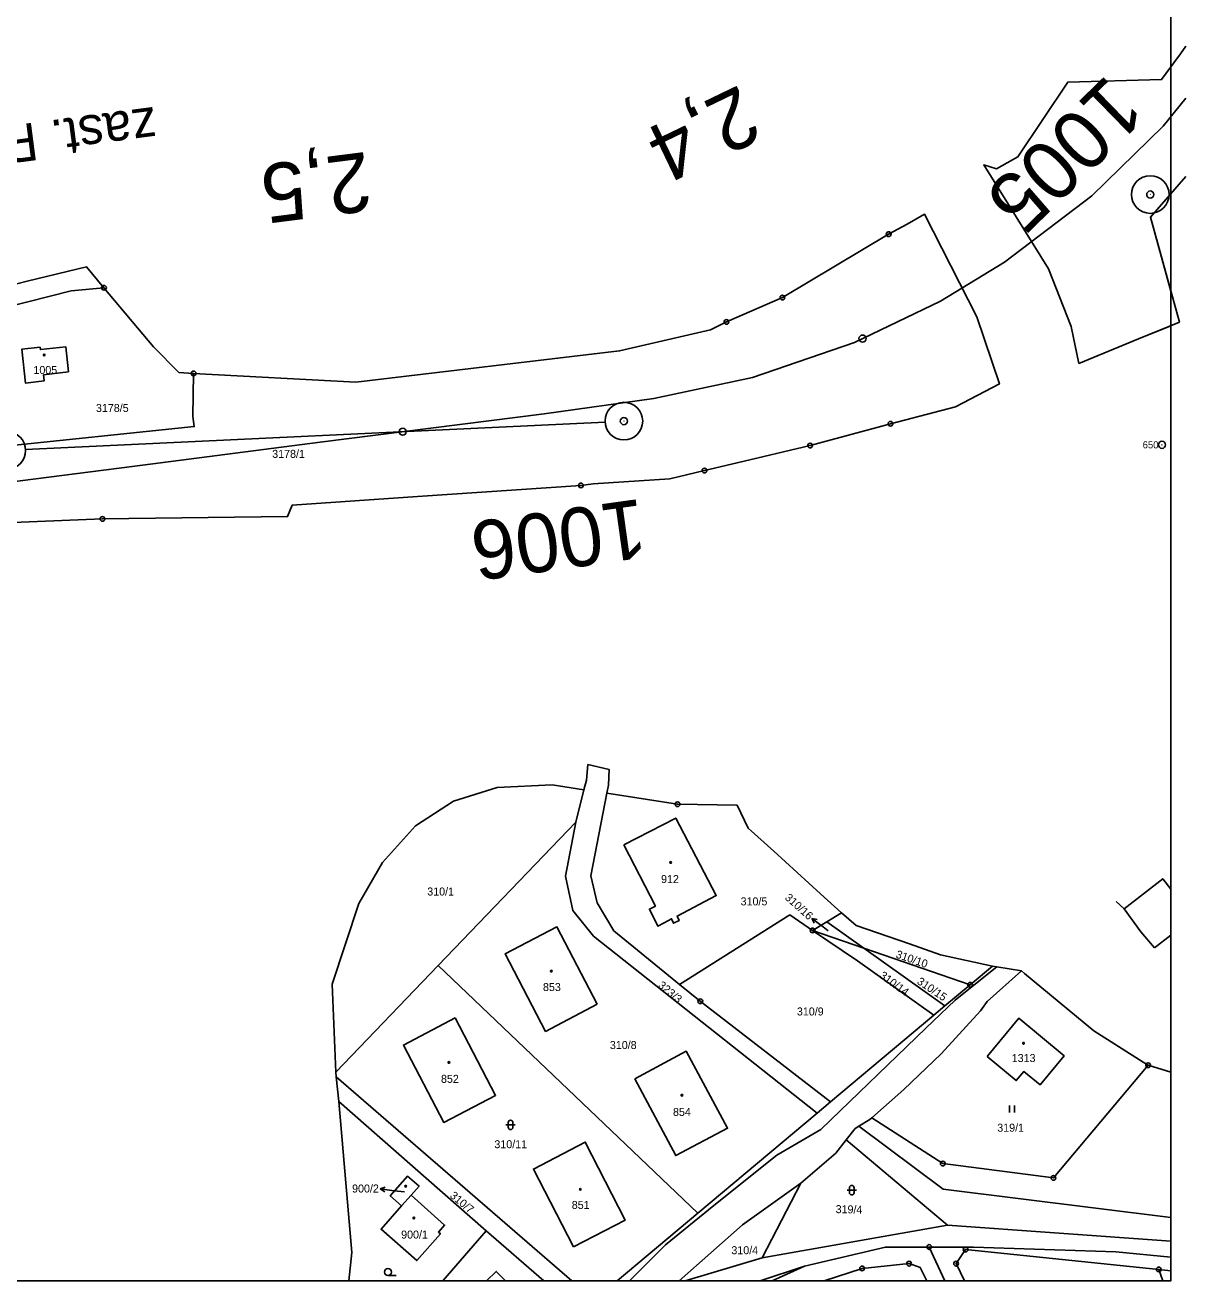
# Model space of a CAD drawing. Extents: x -728802 to -728097, y -1073200 to -1072700.
# Drawn here: x -728343.6 to -728096.8, y -1073200 to -1072933.2 of the extents above; entities that cross this region are included whole.
import ezdxf

# ---------------------------------------------------------------- set-up
doc = ezdxf.new("R2010")
doc.units = 0
for name, color, linetype in [('A5_JŽM', 7, 'Continuous'), ('body_ZBP', 7, 'Continuous'), ('Hranice parcel', 7, 'Continuous'), ('K_31_listy_JŽM', 7, 'Continuous'), ('Pop  PČ popisy', 7, 'Continuous')]:
    doc.layers.add(name, color=color, linetype=linetype)

msp = doc.modelspace()

# ---------------------------------------------------------------- linework, layer by layer
at = {"layer": 'A5_JŽM'}
msp.add_line((-728160.01, -1072977.57), (-728159.91, -1072977.57), dxfattribs=at)
for points in [[(-728096.8, -1072965.33), (-728104.34, -1072973.98), (-728098.16, -1072996.31), (-728106.84, -1072999.82), (-728119.54, -1073005.05), (-728121.2, -1072997.23), (-728125.99, -1072984.92), (-728139.74, -1072962.82), (-728137.07, -1072963.68), (-728132.51, -1072961.17), (-728121.91, -1072945.25), (-728101.97, -1072944.72), (-728097.95, -1072939.25), (-728096.8, -1072937.65)], [(-728096.8, -1072948.67), (-728101.61, -1072954.64), (-728116.81, -1072969.46), (-728135.35, -1072983.51), (-728148.98, -1072991.79), (-728167.22, -1073000.57), (-728188.91, -1073008), (-728209.93, -1073012.47), (-728233.25, -1073015.72), (-728280.82, -1073021.79), (-728320.8, -1073026.91), (-728374.01, -1073033.72)], [(-728326.79, -1072988.95), (-728316.3, -1073001.5), (-728310.91, -1073006.97), (-728307.76, -1073007.16), (-728273.27, -1073008.99), (-728217.2, -1073002.39), (-728197.86, -1072997.89), (-728194.47, -1072996.23), (-728182.58, -1072991.05), (-728160.01, -1072977.6), (-728156.05, -1072975.45), (-728152.39, -1072973.29), (-728141.21, -1072995.16), (-728136.45, -1073009.39), (-728145.77, -1073014.29), (-728159.61, -1073017.87), (-728176.68, -1073022.51), (-728192.2, -1073026.16), (-728199.14, -1073027.8), (-728206.51, -1073029.56), (-728222.82, -1073030.66), (-728225.41, -1073030.96), (-728260.11, -1073033.32), (-728286.78, -1073035.13), (-728287.77, -1073037.59), (-728327.13, -1073038.08), (-728361.73, -1073039.5)], [(-728498.81, -1073037.92), (-728499.78, -1073032.61), (-728497.54, -1073030.15), (-728493.68, -1073027.94), (-728443.97, -1073014.59), (-728443.68, -1073014.51), (-728441.09, -1073023.23), (-728428.92, -1073019.94), (-728429.82, -1073016.43), (-728427.49, -1073015.84), (-728421.24, -1073014.23), (-728422.34, -1073010.27), (-728422.77, -1073008.34), (-728418.21, -1073007), (-728380.57, -1072997.2), (-728343.1, -1072987.57), (-728330.49, -1072984.52), (-728326.79, -1072988.95)]]:
    msp.add_lwpolyline(points, dxfattribs=at)
for centre, radius in [((-728159.96, -1072977.57), 0.499), ((-728165.54, -1072999.76), 0.75), ((-728263.28, -1073019.55), 0.75)]:
    msp.add_circle(centre, radius, dxfattribs=at)
at = {"layer": 'body_ZBP'}
for p, q in [((-728104.34, -1072969.11), (-728104.41, -1072969.18)), ((-728343.46, -1073023.35), (-728220.26, -1073017.49)), ((-728216.22, -1073017.29), (-728216.31, -1073017.3))]:
    msp.add_line(p, q, dxfattribs=at)
for centre, radius in [((-728104.37, -1072969.15), 4), ((-728104.37, -1072969.15), 0.756), ((-728216.27, -1073017.3), 4), ((-728216.27, -1073017.3), 0.756), ((-728347.46, -1073023.54), 4)]:
    msp.add_circle(centre, radius, dxfattribs=at)
at = {"layer": 'Hranice parcel'}
for p, q in [((-728176.68, -1073022.51), (-728192.19, -1073026.18)), ((-728192.19, -1073026.18), (-728199.14, -1073027.8)), ((-728226.46, -1073102.53), (-728224.75, -1073095.65)), ((-728255.72, -1073132.95), (-728226.46, -1073102.53)), ((-728109.91, -1073120.91), (-728101.72, -1073114.55)), ((-728101.72, -1073114.55), (-728100, -1073116.76)), ((-728109.91, -1073120.91), (-728111.61, -1073119.36)), ((-728204.42, -1073137), (-728180.96, -1073122.24)), ((-728180.96, -1073122.24), (-728176.14, -1073125.53)), ((-728173.13, -1073123.69), (-728169.99, -1073121.77)), ((-728166.88, -1073124.49), (-728169.99, -1073121.77)), ((-728176.14, -1073125.53), (-728173.13, -1073123.69)), ((-728173.13, -1073123.69), (-728165.28, -1073129.28)), ((-728165.28, -1073129.28), (-728176.14, -1073125.53)), ((-728166.58, -1073132), (-728176.14, -1073125.53)), ((-728103.47, -1073129.22), (-728106.4, -1073125.8)), ((-728100, -1073126.52), (-728103.47, -1073129.22)), ((-728103.47, -1073129.22), (-728100, -1073126.52)), ((-728148.01, -1073141.57), (-728165.28, -1073129.28)), ((-728165.28, -1073129.28), (-728142.67, -1073137.09)), ((-728277.54, -1073155.64), (-728255.72, -1073132.95)), ((-728255.72, -1073132.95), (-728200.53, -1073185.62)), ((-728150.39, -1073143.57), (-728166.58, -1073132)), ((-728137.92, -1073133.11), (-728148.93, -1073130.68)), ((-728142.67, -1073137.09), (-728137.92, -1073133.11)), ((-728136.99, -1073133.27), (-728137.92, -1073133.11)), ((-728136.99, -1073133.27), (-728137.64, -1073133.79)), ((-728131.74, -1073134.15), (-728136.99, -1073133.27)), ((-728131.09, -1073134.68), (-728131.74, -1073134.15)), ((-728142.67, -1073137.09), (-728148.01, -1073141.57)), ((-728172.33, -1073161.97), (-728150.39, -1073143.57)), ((-728148.01, -1073141.57), (-728150.39, -1073143.57)), ((-728124.97, -1073178.11), (-728104.83, -1073154.17)), ((-728277.54, -1073155.64), (-728277.43, -1073156.67)), ((-728227.3, -1073200), (-728277.43, -1073156.67)), ((-728277.43, -1073156.67), (-728276.88, -1073161.86)), ((-728245.52, -1073189.36), (-728276.88, -1073161.86)), ((-728175.16, -1073164.35), (-728172.33, -1073161.97)), ((-728200.53, -1073185.62), (-728175.16, -1073164.35)), ((-728164, -1073165.73), (-728163.55, -1073165.34)), ((-728134.26, -1073164.22), (-728134.26, -1073162.72)), ((-728133.26, -1073164.22), (-728133.26, -1073162.72)), ((-728241.37, -1073166.86), (-728239.37, -1073166.86)), ((-728240.87, -1073166.36), (-728240.87, -1073167.36)), ((-728239.87, -1073167.36), (-728239.87, -1073166.36)), ((-728166.31, -1073167.13), (-728164, -1073165.73)), ((-728169.03, -1073170.06), (-728171.2, -1073172.84)), ((-728147.48, -1073188.16), (-728169.03, -1073170.06)), ((-728171.2, -1073172.84), (-728178.64, -1073179.24)), ((-728178.64, -1073179.24), (-728191.04, -1073188.08)), ((-728186.87, -1073195.13), (-728178.64, -1073179.24)), ((-728168.82, -1073180.72), (-728166.82, -1073180.72)), ((-728168.32, -1073180.22), (-728168.32, -1073181.22)), ((-728167.32, -1073181.22), (-728167.32, -1073180.22)), ((-728261.51, -1073181.82), (-728263.51, -1073184.08)), ((-728217.67, -1073200), (-728200.53, -1073185.62)), ((-728245.52, -1073189.36), (-728254.78, -1073200)), ((-728191.04, -1073188.08), (-728204.54, -1073200)), ((-728186.87, -1073195.13), (-728147.48, -1073188.16)), ((-728148.01, -1073200), (-728151.36, -1073192.8)), ((-728203.27, -1073200), (-728186.87, -1073195.13)), ((-728266.43, -1073198.87), (-728264.68, -1073198.87)), ((-728102.56, -1073197.57), (-728101.69, -1073200))]:
    msp.add_line(p, q, dxfattribs=at)
for points in [[(-728100, -1072942.04), (-728101.97, -1072944.72), (-728121.91, -1072945.25), (-728132.51, -1072961.17), (-728137.07, -1072963.68), (-728139.74, -1072962.82), (-728125.99, -1072984.92), (-728121.2, -1072997.23), (-728119.54, -1073005.05), (-728106.84, -1072999.82), (-728100, -1072997.05)], [(-728100, -1072989.66), (-728104.34, -1072973.98), (-728100, -1072969)], [(-728361.73, -1073039.5), (-728327.13, -1073038.08), (-728287.77, -1073037.59), (-728286.78, -1073035.13), (-728260.11, -1073033.32), (-728225.41, -1073030.96), (-728222.82, -1073030.66), (-728206.51, -1073029.56), (-728199.14, -1073027.8), (-728192.2, -1073026.16), (-728176.68, -1073022.51), (-728159.61, -1073017.87), (-728145.77, -1073014.29), (-728136.45, -1073009.39), (-728141.21, -1072995.16), (-728152.39, -1072973.29), (-728156.05, -1072975.45), (-728160.01, -1072977.6), (-728182.58, -1072991.05), (-728194.47, -1072996.23), (-728197.86, -1072997.89), (-728217.2, -1073002.39), (-728273.27, -1073008.99), (-728307.76, -1073007.16)], [(-728326.79, -1072988.95), (-728330.49, -1072984.52), (-728343.1, -1072987.57)], [(-728343.1, -1072987.57), (-728380.57, -1072997.2), (-728418.21, -1073007)], [(-728326.79, -1072988.95), (-728333.76, -1072989.63), (-728347.72, -1072993.16)], [(-728307.76, -1073007.16), (-728310.91, -1073006.97), (-728316.3, -1073001.5), (-728326.79, -1072988.95)], [(-728334.31, -1073006.83), (-728334.91, -1073001.49), (-728340.31, -1073002.1), (-728340.37, -1073001.6), (-728344.29, -1073002.04), (-728343.48, -1073009.22), (-728339.54, -1073008.76), (-728339.67, -1073007.5), (-728334.31, -1073006.83)], [(-728307.76, -1073007.16), (-728307.91, -1073016.3), (-728307.59, -1073018.47), (-728349.85, -1073022.84)], [(-728219.9, -1073096.39), (-728219.57, -1073094.69), (-728219.39, -1073091.35), (-728223.93, -1073090.27), (-728224.24, -1073093.59), (-728224.75, -1073095.65)], [(-728224.75, -1073095.65), (-728231.54, -1073094.6), (-728243.19, -1073095.13), (-728252.52, -1073098.07), (-728260.54, -1073103.31), (-728267.61, -1073111.12), (-728272.6, -1073119.79), (-728278.25, -1073136.92), (-728277.54, -1073155.64)], [(-728219.9, -1073096.39), (-728223.33, -1073113.95), (-728221.93, -1073119.67), (-728218.41, -1073125.63), (-728204.42, -1073137)], [(-728169.99, -1073121.77), (-728174.46, -1073117.72), (-728184.37, -1073108.72), (-728189.82, -1073103.77), (-728192.2, -1073098.91), (-728204.86, -1073098.7), (-728219.9, -1073096.39)], [(-728175.16, -1073164.35), (-728222.71, -1073126.75), (-728227.15, -1073121.3), (-728228.65, -1073114.01), (-728226.46, -1073102.53)], [(-728216.3, -1073107.35), (-728205.25, -1073101.64), (-728196.65, -1073118.12), (-728204.97, -1073122.49), (-728204.5, -1073123.39), (-728205.69, -1073124), (-728206.13, -1073123.05), (-728207.71, -1073123.88), (-728209.08, -1073124.6), (-728210.86, -1073121.01), (-728209.58, -1073120.34), (-728216.3, -1073107.35)], [(-728100, -1073116.76), (-728101.72, -1073114.55), (-728109.91, -1073120.91)], [(-728103.47, -1073129.22), (-728106.4, -1073125.8), (-728109.91, -1073120.91)], [(-728221.93, -1073141.17), (-728232.91, -1073146.98), (-728241.52, -1073130.53), (-728230.52, -1073124.78), (-728221.93, -1073141.17)], [(-728148.93, -1073130.68), (-728155.58, -1073128.39), (-728166.88, -1073124.49)], [(-728137.64, -1073133.79), (-728145.84, -1073140.35), (-728152.06, -1073146.3), (-728174.41, -1073167.82), (-728183.77, -1073173.29), (-728197.13, -1073184), (-728207.41, -1073192.34), (-728215.1, -1073200)], [(-728131.74, -1073134.15), (-728139.03, -1073140.65), (-728140.49, -1073142.6), (-728148.8, -1073151.75), (-728156.73, -1073159.33), (-728163.55, -1073165.34)], [(-728104.83, -1073154.17), (-728105.88, -1073153.51), (-728116.39, -1073146.9), (-728131.09, -1073134.68)], [(-728204.42, -1073137), (-728200.02, -1073140.57), (-728172.33, -1073161.97)], [(-728252.12, -1073144.13), (-728243.56, -1073160.6), (-728254.57, -1073166.32), (-728263.13, -1073149.88), (-728252.12, -1073144.13)], [(-728139.06, -1073152.3), (-728132.34, -1073144.18), (-728122.67, -1073152.19), (-728127.8, -1073158.37), (-728131.25, -1073155.52), (-728132.86, -1073157.42), (-728139.06, -1073152.3)], [(-728213.93, -1073157.03), (-728203, -1073151.22), (-728194.23, -1073167.57), (-728205.24, -1073173.38), (-728213.93, -1073157.03)], [(-728100, -1073155.63), (-728104.83, -1073154.17)], [(-728276.88, -1073161.86), (-728274.11, -1073193.97), (-728274.71, -1073200)], [(-728163.55, -1073165.34), (-728148.47, -1073175.06), (-728124.97, -1073178.11)], [(-728166.31, -1073167.13), (-728167.11, -1073167.62), (-728169.03, -1073170.06)], [(-728100, -1073186.54), (-728148.42, -1073180.48), (-728166.31, -1073167.13)], [(-728227.01, -1073192.74), (-728235.51, -1073176.24), (-728224.47, -1073170.52), (-728215.97, -1073187.07), (-728227.01, -1073192.74)], [(-728263.51, -1073184.08), (-728265.94, -1073181.94), (-728262.28, -1073177.75), (-728259.8, -1073179.86), (-728261.51, -1073181.82)], [(-728261.51, -1073181.82), (-728254.37, -1073188.13), (-728255.69, -1073189.64), (-728255.28, -1073190), (-728260.26, -1073195.7), (-728267.88, -1073189.03), (-728263.51, -1073184.08)], [(-728233.29, -1073200), (-728245.52, -1073189.36)], [(-728147.48, -1073188.16), (-728100, -1073191.54)], [(-728177.91, -1073196.9), (-728160.67, -1073192.8), (-728151.36, -1073192.8)], [(-728151.36, -1073192.8), (-728141.97, -1073192.8), (-728111.66, -1073193.86), (-728100, -1073194.94)], [(-728143.84, -1073200), (-728145.64, -1073196.34), (-728143.64, -1073193.34), (-728102.56, -1073197.57)], [(-728177.91, -1073196.9), (-728187.28, -1073200)], [(-728184.77, -1073200), (-728177.91, -1073196.9)], [(-728173.71, -1073200), (-728165.64, -1073197.34), (-728155.64, -1073196.34), (-728153.27, -1073197.13), (-728151.86, -1073200)], [(-728245.45, -1073200), (-728243.42, -1073197.98), (-728241.41, -1073200)], [(-728100, -1073197.83), (-728102.56, -1073197.57)]]:
    msp.add_lwpolyline(points, dxfattribs=at)
for centre, radius in [((-728160.01, -1072977.6), 0.5), ((-728160.01, -1072977.6), 0.0303), ((-728326.79, -1072988.95), 0.5), ((-728326.79, -1072988.95), 0.0303), ((-728182.58, -1072991.05), 0.5), ((-728182.58, -1072991.05), 0.0303), ((-728194.47, -1072996.23), 0.5), ((-728194.47, -1072996.23), 0.0303), ((-728339.5, -1073003.26), 0.175), ((-728307.76, -1073007.16), 0.5), ((-728307.76, -1073007.16), 0.0303), ((-728159.61, -1073017.87), 0.5), ((-728159.61, -1073017.87), 0.0303), ((-728176.68, -1073022.51), 0.5), ((-728176.68, -1073022.51), 0.0303), ((-728101.88, -1073022.34), 0.75), ((-728101.88, -1073022.34), 0.03), ((-728199.14, -1073027.8), 0.5), ((-728199.14, -1073027.8), 0.0303), ((-728225.41, -1073030.96), 0.5), ((-728225.41, -1073030.96), 0.0303), ((-728327.13, -1073038.08), 0.5), ((-728327.13, -1073038.08), 0.0303), ((-728204.86, -1073098.7), 0.5), ((-728204.86, -1073098.7), 0.0303), ((-728206.31, -1073111.08), 0.175), ((-728176.14, -1073125.53), 0.5), ((-728176.14, -1073125.53), 0.0303), ((-728231.7, -1073134.18), 0.175), ((-728142.67, -1073137.09), 0.5), ((-728142.67, -1073137.09), 0.0303), ((-728200.02, -1073140.57), 0.5), ((-728200.02, -1073140.57), 0.0303), ((-728131.32, -1073149.5), 0.175), ((-728253.47, -1073153.58), 0.175), ((-728104.83, -1073154.17), 0.5), ((-728104.83, -1073154.17), 0.0303), ((-728203.94, -1073160.54), 0.175), ((-728148.47, -1073175.06), 0.5), ((-728148.47, -1073175.06), 0.0303), ((-728124.97, -1073178.11), 0.5), ((-728124.97, -1073178.11), 0.0303), ((-728262.66, -1073179.88), 0.175), ((-728225.52, -1073180.53), 0.175), ((-728260.91, -1073186.65), 0.175), ((-728151.36, -1073192.8), 0.5), ((-728151.36, -1073192.8), 0.0303), ((-728143.64, -1073193.34), 0.5), ((-728143.64, -1073193.34), 0.0303), ((-728266.43, -1073198.12), 0.75), ((-728165.64, -1073197.34), 0.5), ((-728165.64, -1073197.34), 0.0303), ((-728155.64, -1073196.34), 0.5), ((-728155.64, -1073196.34), 0.0303), ((-728145.64, -1073196.34), 0.5), ((-728145.64, -1073196.34), 0.0303), ((-728102.56, -1073197.57), 0.5), ((-728102.56, -1073197.57), 0.0303)]:
    msp.add_circle(centre, radius, dxfattribs=at)
for centre, start, end in [((-728240.37, -1073166.36), 0, 180), ((-728240.37, -1073167.36), 180, 359.9879), ((-728167.82, -1073180.22), 0, 180), ((-728167.82, -1073181.22), 180, 359.9879)]:
    msp.add_arc(centre, 0.5, start, end, dxfattribs=at)
at = {"layer": 'K_31_listy_JŽM'}
msp.add_lwpolyline([(-728800, -1073200), (-728800, -1072700), (-728100, -1072700), (-728100, -1073200), (-728800, -1073200)], dxfattribs=at)
at = {"layer": 'Pop  PČ popisy'}
for p, q in [((-728173.89, -1073124.78), (-728176.29, -1073122.97)), ((-728176.29, -1073122.97), (-728175.19, -1073123.18)), ((-728176.29, -1073122.97), (-728175.79, -1073123.98)), ((-728172.83, -1073125.59), (-728173.89, -1073124.78)), ((-728268.05, -1073180.47), (-728266.99, -1073180.1)), ((-728265.07, -1073180.84), (-728268.05, -1073180.47)), ((-728268.05, -1073180.47), (-728267.12, -1073181.09)), ((-728262.93, -1073181.1), (-728265.07, -1073180.84))]:
    msp.add_line(p, q, dxfattribs=at)

# ---------------------------------------------------------------- texts
at = {"layer": 'A5_JŽM'}
for s, height, rotation, p in [('2,4', 12.5, 205.6852, (-728191.55, -1072945.69)), ('zast. Poříčí nad Sázavou', 8, 187.4528, (-728316.1, -1072950.5)), ('2,5', 12.5, 187.283, (-728270.89, -1072960.04))]:
    msp.add_text(s, height=height, rotation=rotation, dxfattribs=at).set_placement(p)
at = {"layer": 'body_ZBP'}
for s, rotation, p in [('1005', 224.2749, (-728113.42, -1072943.35)), ('1006', 187.9323, (-728212.51, -1073033.76))]:
    msp.add_text(s, height=12.5, rotation=rotation, dxfattribs=at).set_placement(p)
at = {"layer": 'Hranice parcel'}
for s, height, p in [('1005', 1.7, (-728341.79, -1073007.29)), ('3178/5', 1.7, (-728328.5, -1073015.36)), ('3178/1', 1.7, (-728291.03, -1073025.11)), ('650', 1.5, (-728105.98, -1073023.09)), ('912', 1.7, (-728208.37, -1073115.46)), ('310/1', 1.7, (-728258.07, -1073118.11)), ('310/5', 1.7, (-728191.46, -1073120.21)), ('853', 1.7, (-728233.47, -1073138.41)), ('310/9', 1.7, (-728179.49, -1073143.6)), ('310/8', 1.7, (-728219.25, -1073150.73)), ('1313', 1.7, (-728133.82, -1073153.5)), ('852', 1.7, (-728255.15, -1073157.92)), ('854', 1.7, (-728205.83, -1073164.95)), ('319/1', 1.7, (-728136.9, -1073168.3)), ('310/11', 1.7, (-728243.8, -1073171.81)), ('900/2', 1.7, (-728274.05, -1073181.22)), ('851', 1.7, (-728227.35, -1073184.71)), ('900/1', 1.7, (-728263.62, -1073191.01)), ('310/4', 1.7, (-728193.42, -1073194.33))]:
    msp.add_text(s, height=height, dxfattribs=at).set_placement(p)
for s, rotation, p in [('310/16', 318, (-728182.18, -1073118.77)), ('310/10', 341, (-728158.6, -1073131.28)), ('310/14', 324, (-728162.08, -1073135.45)), ('310/15', 326, (-728154.11, -1073136.75)), ('323/3', 320, (-728209.15, -1073137.43)), ('310/7', 320, (-728253.39, -1073182.12)), ('319/4', 359, (-728171.27, -1073185.6))]:
    msp.add_text(s, height=1.7, rotation=rotation, dxfattribs=at).set_placement(p)

doc.saveas('drawing.dxf')
